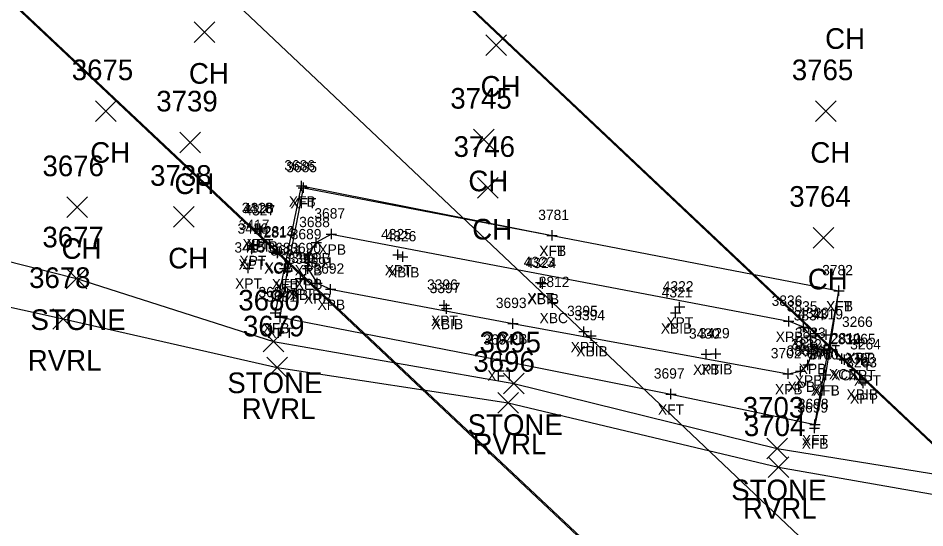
# Model space of a CAD drawing. Extents: x 1647574 to 1652703, y 212895 to 228670.
# Drawn here: x 1648808.6 to 1648896.4, y 227207.7 to 227257.1 of the extents above; entities that cross this region are included whole.
import ezdxf

# ---------------------------------------------------------------- set-up
doc = ezdxf.new("R2010")
doc.units = 0
for name, color, linetype in [('B_A', 7, 'Continuous'), ('B_I', 7, 'Continuous'), ('B_TIC', 7, 'Continuous'), ('BDC', 7, 'Continuous'), ('BELB', 7, 'Continuous'), ('BFT', 7, 'Continuous'), ('BSUBM', 7, 'Continuous'), ('L_A', 7, 'Continuous'), ('L_I', 7, 'Continuous'), ('L_TIC', 7, 'Continuous'), ('LASF', 7, 'Continuous'), ('LAWE', 7, 'Continuous')]:
    doc.layers.add(name, color=color, linetype=linetype)

msp = doc.modelspace()

# ---------------------------------------------------------------- linework, layer by layer
at = {"layer": 'B_TIC'}
for p, q in [((1648836.021, 227240.799), (1648836.096, 227240.799)), ((1648836.186, 227240.634), (1648836.262, 227240.634)), ((1648831.568, 227236.672), (1648831.644, 227236.672)), ((1648831.972, 227236.664), (1648832.048, 227236.664)), ((1648832.105, 227236.447), (1648832.18, 227236.447)), ((1648837.431, 227235.312), (1648837.506, 227235.312)), ((1648838.906, 227236.148), (1648838.982, 227236.148)), ((1648838.906, 227236.148), (1648838.982, 227236.148)), ((1648860.274, 227236.008), (1648860.35, 227236.008)), ((1648860.274, 227236.008), (1648860.35, 227236.008)), ((1648831.185, 227234.682), (1648831.261, 227234.682)), ((1648831.278, 227235.038), (1648831.354, 227235.038)), ((1648833.667, 227234.301), (1648833.743, 227234.301)), ((1648833.716, 227234.413), (1648833.792, 227234.413)), ((1648836.621, 227234.138), (1648836.696, 227234.138)), ((1648845.348, 227234.141), (1648845.423, 227234.141)), ((1648845.803, 227233.942), (1648845.878, 227233.942)), ((1648830.857, 227232.852), (1648830.932, 227232.852)), ((1648834.37, 227232.806), (1648834.445, 227232.806)), ((1648836.619, 227232.795), (1648836.694, 227232.795)), ((1648834.645, 227232.568), (1648834.72, 227232.568)), ((1648835.9, 227231.842), (1648835.975, 227231.842)), ((1648836.301, 227231.765), (1648836.376, 227231.765)), ((1648837.508, 227231.398), (1648837.583, 227231.398)), ((1648859.146, 227231.443), (1648859.222, 227231.443)), ((1648859.329, 227231.35), (1648859.404, 227231.35)), ((1648838.819, 227230.806), (1648838.895, 227230.806)), ((1648888.046, 227230.653), (1648888.122, 227230.653)), ((1648888.046, 227230.653), (1648888.122, 227230.653)), ((1648888.046, 227230.653), (1648888.122, 227230.653)), ((1648849.822, 227229.253), (1648849.898, 227229.253)), ((1648860.321, 227229.513), (1648860.396, 227229.513)), ((1648833.489, 227228.524), (1648833.564, 227228.524)), ((1648850.045, 227228.925), (1648850.121, 227228.925)), ((1648872.223, 227228.51), (1648872.299, 227228.51)), ((1648872.612, 227229.082), (1648872.688, 227229.082)), ((1648833.956, 227228.091), (1648834.031, 227228.091)), ((1648833.956, 227228.091), (1648834.031, 227228.091)), ((1648856.473, 227227.48), (1648856.549, 227227.48)), ((1648883.184, 227227.695), (1648883.259, 227227.695)), ((1648883.184, 227227.695), (1648883.259, 227227.695)), ((1648863.348, 227226.705), (1648863.424, 227226.705)), ((1648884.621, 227227.143), (1648884.697, 227227.143)), ((1648864.042, 227226.291), (1648864.118, 227226.291)), ((1648885.289, 227226.282), (1648885.364, 227226.282)), ((1648885.777, 227226.52), (1648885.853, 227226.52)), ((1648886.812, 227226.391), (1648886.887, 227226.391)), ((1648890.016, 227225.653), (1648890.091, 227225.653)), ((1648855.259, 227223.94), (1648855.334, 227223.94)), ((1648875.196, 227224.513), (1648875.271, 227224.513)), ((1648876.117, 227224.549), (1648876.192, 227224.549)), ((1648885.412, 227224.59), (1648885.487, 227224.59)), ((1648888.334, 227224.067), (1648888.409, 227224.067)), ((1648888.576, 227223.976), (1648888.651, 227223.976)), ((1648890.269, 227223.986), (1648890.345, 227223.986)), ((1648885.032, 227223.467), (1648885.108, 227223.467)), ((1648890.782, 227223.47), (1648890.858, 227223.47)), ((1648883.11, 227222.615), (1648883.186, 227222.615)), ((1648884.329, 227222.86), (1648884.405, 227222.86)), ((1648886.59, 227222.504), (1648886.665, 227222.504)), ((1648886.758, 227222.506), (1648886.834, 227222.506)), ((1648890.207, 227222.105), (1648890.282, 227222.105)), ((1648890.395, 227221.734), (1648890.471, 227221.734)), ((1648871.77, 227220.649), (1648871.845, 227220.649)), ((1648885.674, 227217.353), (1648885.75, 227217.353)), ((1648885.713, 227217.693), (1648885.788, 227217.693))]:
    msp.add_line(p, q, dxfattribs=at)
for points in [[(1648835.517, 227240.799), (1648836.517, 227240.799)], [(1648835.683, 227240.634), (1648836.683, 227240.634)], [(1648836.017, 227240.299), (1648836.017, 227241.299)], [(1648836.183, 227240.134), (1648836.183, 227241.134)], [(1648831.565, 227236.172), (1648831.565, 227237.172)], [(1648831.969, 227236.164), (1648831.969, 227237.164)], [(1648831.065, 227236.672), (1648832.065, 227236.672)], [(1648831.469, 227236.664), (1648832.469, 227236.664)], [(1648831.601, 227236.447), (1648832.601, 227236.447)], [(1648832.101, 227235.947), (1648832.101, 227236.947)], [(1648838.903, 227235.648), (1648838.903, 227236.648)], [(1648838.903, 227235.648), (1648838.903, 227236.648)], [(1648860.271, 227235.508), (1648860.271, 227236.508)], [(1648860.271, 227235.508), (1648860.271, 227236.508)], [(1648831.275, 227234.538), (1648831.275, 227235.538)], [(1648836.927, 227235.312), (1648837.927, 227235.312)], [(1648837.427, 227234.812), (1648837.427, 227235.812)], [(1648838.403, 227236.148), (1648839.403, 227236.148)], [(1648838.403, 227236.148), (1648839.403, 227236.148)], [(1648859.771, 227236.008), (1648860.771, 227236.008)], [(1648859.771, 227236.008), (1648860.771, 227236.008)], [(1648830.682, 227234.682), (1648831.682, 227234.682)], [(1648830.775, 227235.038), (1648831.775, 227235.038)], [(1648831.182, 227234.182), (1648831.182, 227235.182)], [(1648833.664, 227233.801), (1648833.664, 227234.801)], [(1648833.713, 227233.913), (1648833.713, 227234.913)], [(1648836.617, 227233.638), (1648836.617, 227234.638)], [(1648845.344, 227233.641), (1648845.344, 227234.641)], [(1648845.799, 227233.442), (1648845.799, 227234.442)], [(1648833.164, 227234.301), (1648834.164, 227234.301)], [(1648833.213, 227234.413), (1648834.213, 227234.413)], [(1648836.117, 227234.138), (1648837.117, 227234.138)], [(1648844.844, 227234.141), (1648845.844, 227234.141)], [(1648845.299, 227233.942), (1648846.299, 227233.942)], [(1648830.353, 227232.852), (1648831.353, 227232.852)], [(1648830.853, 227232.352), (1648830.853, 227233.352)], [(1648833.866, 227232.806), (1648834.866, 227232.806)], [(1648834.366, 227232.306), (1648834.366, 227233.306)], [(1648834.641, 227232.068), (1648834.641, 227233.068)], [(1648836.115, 227232.795), (1648837.115, 227232.795)], [(1648836.615, 227232.295), (1648836.615, 227233.295)], [(1648834.141, 227232.568), (1648835.141, 227232.568)], [(1648835.396, 227231.842), (1648836.396, 227231.842)], [(1648835.896, 227231.342), (1648835.896, 227232.342)], [(1648836.297, 227231.265), (1648836.297, 227232.265)], [(1648837.504, 227230.898), (1648837.504, 227231.898)], [(1648859.143, 227230.943), (1648859.143, 227231.943)], [(1648859.326, 227230.85), (1648859.326, 227231.85)], [(1648835.797, 227231.765), (1648836.797, 227231.765)], [(1648837.004, 227231.398), (1648838.004, 227231.398)], [(1648838.816, 227230.306), (1648838.816, 227231.306)], [(1648858.643, 227231.443), (1648859.643, 227231.443)], [(1648858.826, 227231.35), (1648859.826, 227231.35)], [(1648888.043, 227230.153), (1648888.043, 227231.153)], [(1648888.043, 227230.153), (1648888.043, 227231.153)], [(1648888.043, 227230.153), (1648888.043, 227231.153)], [(1648838.316, 227230.806), (1648839.316, 227230.806)], [(1648887.543, 227230.653), (1648888.543, 227230.653)], [(1648887.543, 227230.653), (1648888.543, 227230.653)], [(1648887.543, 227230.653), (1648888.543, 227230.653)], [(1648849.319, 227229.253), (1648850.319, 227229.253)], [(1648849.819, 227228.753), (1648849.819, 227229.753)], [(1648850.042, 227228.425), (1648850.042, 227229.425)], [(1648859.817, 227229.513), (1648860.817, 227229.513)], [(1648860.317, 227229.013), (1648860.317, 227230.013)], [(1648872.609, 227228.582), (1648872.609, 227229.582)], [(1648832.985, 227228.524), (1648833.985, 227228.524)], [(1648833.485, 227228.024), (1648833.485, 227229.024)], [(1648833.952, 227227.591), (1648833.952, 227228.591)], [(1648833.952, 227227.591), (1648833.952, 227228.591)], [(1648849.542, 227228.925), (1648850.542, 227228.925)], [(1648871.72, 227228.51), (1648872.72, 227228.51)], [(1648872.109, 227229.082), (1648873.109, 227229.082)], [(1648872.22, 227228.01), (1648872.22, 227229.01)], [(1648833.452, 227228.091), (1648834.452, 227228.091)], [(1648833.452, 227228.091), (1648834.452, 227228.091)], [(1648855.97, 227227.48), (1648856.97, 227227.48)], [(1648856.47, 227226.98), (1648856.47, 227227.98)], [(1648882.68, 227227.695), (1648883.68, 227227.695)], [(1648882.68, 227227.695), (1648883.68, 227227.695)], [(1648883.18, 227227.195), (1648883.18, 227228.195)], [(1648883.18, 227227.195), (1648883.18, 227228.195)], [(1648884.618, 227226.643), (1648884.618, 227227.643)], [(1648862.845, 227226.705), (1648863.845, 227226.705)], [(1648863.345, 227226.205), (1648863.345, 227227.205)], [(1648864.039, 227225.791), (1648864.039, 227226.791)], [(1648884.118, 227227.143), (1648885.118, 227227.143)], [(1648885.285, 227225.782), (1648885.285, 227226.782)], [(1648885.774, 227226.02), (1648885.774, 227227.02)], [(1648886.808, 227225.891), (1648886.808, 227226.891)], [(1648863.539, 227226.291), (1648864.539, 227226.291)], [(1648884.785, 227226.282), (1648885.785, 227226.282)], [(1648885.274, 227226.52), (1648886.274, 227226.52)], [(1648886.308, 227226.391), (1648887.308, 227226.391)], [(1648889.512, 227225.653), (1648890.512, 227225.653)], [(1648890.012, 227225.153), (1648890.012, 227226.153)], [(1648875.192, 227224.013), (1648875.192, 227225.013)], [(1648876.113, 227224.049), (1648876.113, 227225.049)], [(1648885.408, 227224.09), (1648885.408, 227225.09)], [(1648854.755, 227223.94), (1648855.755, 227223.94)], [(1648855.255, 227223.44), (1648855.255, 227224.44)], [(1648874.692, 227224.513), (1648875.692, 227224.513)], [(1648875.613, 227224.549), (1648876.613, 227224.549)], [(1648884.908, 227224.59), (1648885.908, 227224.59)], [(1648885.029, 227222.967), (1648885.029, 227223.967)], [(1648887.83, 227224.067), (1648888.83, 227224.067)], [(1648888.072, 227223.976), (1648889.072, 227223.976)], [(1648888.33, 227223.567), (1648888.33, 227224.567)], [(1648888.572, 227223.476), (1648888.572, 227224.476)], [(1648889.766, 227223.986), (1648890.766, 227223.986)], [(1648890.266, 227223.486), (1648890.266, 227224.486)], [(1648890.779, 227222.97), (1648890.779, 227223.97)], [(1648883.107, 227222.115), (1648883.107, 227223.115)], [(1648884.326, 227222.36), (1648884.326, 227223.36)], [(1648884.529, 227223.467), (1648885.529, 227223.467)], [(1648890.279, 227223.47), (1648891.279, 227223.47)], [(1648882.607, 227222.615), (1648883.607, 227222.615)], [(1648883.826, 227222.86), (1648884.826, 227222.86)], [(1648886.086, 227222.504), (1648887.086, 227222.504)], [(1648886.255, 227222.506), (1648887.255, 227222.506)], [(1648886.586, 227222.004), (1648886.586, 227223.004)], [(1648886.755, 227222.006), (1648886.755, 227223.006)], [(1648890.203, 227221.605), (1648890.203, 227222.605)], [(1648890.392, 227221.234), (1648890.392, 227222.234)], [(1648889.703, 227222.105), (1648890.703, 227222.105)], [(1648889.892, 227221.734), (1648890.892, 227221.734)], [(1648871.266, 227220.649), (1648872.266, 227220.649)], [(1648871.766, 227220.149), (1648871.766, 227221.149)], [(1648885.671, 227216.853), (1648885.671, 227217.853)], [(1648885.709, 227217.193), (1648885.709, 227218.193)], [(1648885.171, 227217.353), (1648886.171, 227217.353)], [(1648885.209, 227217.693), (1648886.209, 227217.693)]]:
    msp.add_lwpolyline(points, dxfattribs=at)
at = {"layer": 'BDC'}
for points in [[(1648650.624, 227406.773), (1648690.525, 227369.254), (1648733.472, 227328.732), (1648776.312, 227288.32), (1648833.664, 227234.301), (1648891.231, 227180.054), (1648955.856, 227118.961), (1649002.635, 227075.018), (1649045.277, 227034.596)], [(1648651.076, 227406.804), (1648690.742, 227369.256), (1648733.458, 227328.853), (1648776.322, 227288.427), (1648833.713, 227234.413), (1648891.304, 227180.165), (1648955.952, 227119.198), (1649002.814, 227075.033), (1649045.282, 227034.879)], [(1648705.852, 227396.154), (1648745.059, 227359.411), (1648787.916, 227318.711), (1648830.863, 227278.3), (1648888.33, 227224.067), (1648945.958, 227169.85), (1649010.577, 227108.866), (1649057.241, 227064.803), (1649099.962, 227024.603)], [(1648705.902, 227396.256), (1648745.142, 227359.215), (1648788.072, 227318.717), (1648831.078, 227278.232), (1648888.572, 227223.976), (1648945.897, 227169.932), (1649010.764, 227109.119), (1649057.374, 227064.845), (1649100.019, 227024.673)]]:
    msp.add_lwpolyline(points, dxfattribs=at)
at = {"layer": 'BELB'}
msp.add_lwpolyline([(1648676.128, 227401.909), (1648716.738, 227364.514), (1648759.552, 227324.27), (1648803.456, 227283.214), (1648860.317, 227229.513), (1648917.836, 227175.012), (1648982.231, 227114.435), (1649029.643, 227069.952), (1649071.001, 227030.272)], dxfattribs=at)
at = {"layer": 'BFT'}
for points in [[(1648833.485, 227228.524), (1648834.366, 227232.806), (1648836.017, 227240.799), (1648860.271, 227236.008)], [(1648833.952, 227228.091), (1648834.641, 227232.568), (1648836.183, 227240.634), (1648860.271, 227236.008), (1648888.043, 227230.653)], [(1648833.952, 227228.091), (1648855.255, 227223.94), (1648871.766, 227220.649), (1648885.709, 227217.693), (1648886.586, 227222.504), (1648888.043, 227230.653)], [(1648885.671, 227217.353), (1648886.755, 227222.506), (1648888.043, 227230.653)]]:
    msp.add_lwpolyline(points, dxfattribs=at)
at = {"layer": 'BSUBM'}
for points in [[(1648838.903, 227236.148), (1648837.427, 227235.312), (1648836.617, 227234.138), (1648836.615, 227232.795), (1648837.504, 227231.398), (1648838.816, 227230.806), (1648856.47, 227227.48), (1648883.107, 227222.615), (1648884.326, 227222.86), (1648885.029, 227223.467), (1648885.408, 227224.59), (1648885.285, 227226.282), (1648884.618, 227227.143), (1648883.18, 227227.695)], [(1648838.903, 227236.148), (1648883.18, 227227.695)]]:
    msp.add_lwpolyline(points, dxfattribs=at)
at = {"layer": 'L_TIC'}
for points in [[(1648825.616, 227254.702), (1648827.616, 227256.702)], [(1648827.616, 227254.702), (1648825.616, 227256.702)], [(1648853.857, 227253.45), (1648855.857, 227255.45)], [(1648855.857, 227253.45), (1648853.857, 227255.45)], [(1648816.064, 227247.043), (1648818.064, 227249.043)], [(1648818.064, 227247.043), (1648816.064, 227249.043)], [(1648885.782, 227247.044), (1648887.782, 227249.044)], [(1648887.782, 227247.044), (1648885.782, 227249.044)], [(1648824.212, 227244.017), (1648826.212, 227246.017)], [(1648826.212, 227244.017), (1648824.212, 227246.017)], [(1648852.671, 227244.288), (1648854.671, 227246.288)], [(1648854.671, 227244.288), (1648852.671, 227246.288)], [(1648853.043, 227239.617), (1648855.043, 227241.617)], [(1648855.043, 227239.617), (1648853.043, 227241.617)], [(1648813.284, 227237.746), (1648815.284, 227239.746)], [(1648815.284, 227237.746), (1648813.284, 227239.746)], [(1648823.607, 227236.817), (1648825.607, 227238.817)], [(1648825.607, 227236.817), (1648823.607, 227238.817)], [(1648885.538, 227234.787), (1648887.538, 227236.787)], [(1648887.538, 227234.787), (1648885.538, 227236.787)], [(1648813.223, 227230.854), (1648815.223, 227232.854)], [(1648815.223, 227230.854), (1648813.223, 227232.854)], [(1648811.936, 227226.92), (1648813.936, 227228.92)], [(1648813.936, 227226.92), (1648811.936, 227228.92)], [(1648832.279, 227224.74), (1648834.279, 227226.74)], [(1648834.279, 227224.74), (1648832.279, 227226.74)], [(1648832.651, 227222.234), (1648834.651, 227224.234)], [(1648834.651, 227222.234), (1648832.651, 227224.234)], [(1648855.547, 227220.689), (1648857.547, 227222.689)], [(1648857.547, 227220.689), (1648855.547, 227222.689)], [(1648855.007, 227218.814), (1648857.007, 227220.814)], [(1648857.007, 227218.814), (1648855.007, 227220.814)], [(1648881.063, 227214.369), (1648883.063, 227216.369)], [(1648883.063, 227214.369), (1648881.063, 227216.369)], [(1648881.174, 227212.58), (1648883.174, 227214.58)], [(1648883.174, 227212.58), (1648881.174, 227214.58)]]:
    msp.add_lwpolyline(points, dxfattribs=at)
at = {"layer": 'LASF'}
msp.add_lwpolyline([(1648499.797, 227390.788), (1648534.237, 227361.964), (1648564.139, 227335.998), (1648594.151, 227310.22), (1648628.599, 227293.401), (1648654.269, 227279.63), (1648686.156, 227265.624), (1648717.135, 227256.764), (1648740.627, 227248.949), (1648765.894, 227244.077), (1648814.223, 227231.854), (1648833.279, 227225.74), (1648856.547, 227221.689), (1648882.063, 227215.369), (1648909.355, 227210.97), (1648936.503, 227203.804), (1648961.566, 227198.174), (1648983.303, 227192.864), (1648997.705, 227192.889), (1649002.003, 227200.334)], dxfattribs=at)
at = {"layer": 'LAWE'}
msp.add_lwpolyline([(1648476.378, 227405.216), (1648496.153, 227388.221), (1648530.655, 227356.871), (1648567.867, 227325.979), (1648591.316, 227307.766), (1648628.319, 227290.488), (1648653.198, 227277.298), (1648685.977, 227263.737), (1648715.079, 227253.44), (1648739.533, 227246.568), (1648765.368, 227238.448), (1648812.936, 227227.92), (1648833.651, 227223.234), (1648856.007, 227219.814), (1648882.174, 227213.58), (1648908.492, 227208.957)], dxfattribs=at)

# ---------------------------------------------------------------- texts
at = {"layer": 'B_A'}
for s, p in [('XFB', (1648834.777, 227238.799)), ('XFT', (1648834.927, 227238.634)), ('XPT', (1648830.285, 227234.672)), ('XBIB', (1648830.672, 227234.447)), ('XPT', (1648830.689, 227234.664)), ('XPB', (1648837.639, 227234.148)), ('XPB', (1648837.639, 227234.148)), ('XFT', (1648859.015, 227234.008)), ('XFB', (1648859.031, 227234.008)), ('XPT', (1648829.902, 227232.682)), ('XPT', (1648829.995, 227233.038)), ('XPB', (1648836.163, 227233.312)), ('XCT', (1648832.384, 227232.301)), ('XCB', (1648832.449, 227232.413)), ('XPB', (1648835.354, 227232.138)), ('XPT', (1648844.065, 227232.141)), ('XBIB', (1648844.37, 227231.942)), ('XPT', (1648829.574, 227230.852)), ('XFB', (1648833.126, 227230.806)), ('XPB', (1648835.351, 227230.795)), ('XFT', (1648833.385, 227230.568)), ('XPT', (1648834.617, 227229.842)), ('XBIB', (1648834.868, 227229.765)), ('XPB', (1648836.24, 227229.398)), ('XPT', (1648857.863, 227229.443)), ('XBIB', (1648857.896, 227229.35)), ('XPB', (1648837.552, 227228.806)), ('XFT', (1648886.787, 227228.653)), ('XFT', (1648886.787, 227228.653)), ('XFB', (1648886.802, 227228.653)), ('XBC', (1648859.053, 227227.513)), ('XFB', (1648832.245, 227226.524)), ('XPT', (1648848.539, 227227.253)), ('XBIB', (1648848.613, 227226.925)), ('XBIB', (1648870.791, 227226.51)), ('XPT', (1648871.329, 227227.082)), ('XFT', (1648832.696, 227226.091)), ('XFT', (1648832.696, 227226.091)), ('XPB', (1648881.917, 227225.695)), ('XPB', (1648881.917, 227225.695)), ('XPB', (1648855.206, 227225.48)), ('XPT', (1648862.065, 227224.705)), ('XPB', (1648883.354, 227225.143)), ('XBIB', (1648862.61, 227224.291)), ('XPB', (1648884.022, 227224.282)), ('XBIB', (1648884.345, 227224.52)), ('XPT', (1648885.529, 227224.391)), ('XPT', (1648888.733, 227223.653)), ('XPT', (1648873.913, 227222.513)), ('XBIB', (1648874.684, 227222.549)), ('XPB', (1648884.144, 227222.59)), ('XCB', (1648887.066, 227222.067)), ('XFT', (1648853.999, 227221.94)), ('XPB', (1648883.765, 227221.467)), ('XCT', (1648887.293, 227221.976)), ('XPT', (1648888.986, 227221.986)), ('XPT', (1648889.499, 227221.47)), ('XPB', (1648881.843, 227220.615)), ('XPB', (1648883.062, 227220.86)), ('XFT', (1648885.331, 227220.504)), ('XFB', (1648885.515, 227220.506)), ('XBIB', (1648888.774, 227220.105)), ('XPT', (1648889.112, 227219.734)), ('XFT', (1648870.511, 227218.649)), ('XFB', (1648884.431, 227215.353)), ('XFT', (1648884.453, 227215.693))]:
    msp.add_text(s, height=1, dxfattribs=at).set_placement(p)
at = {"layer": 'B_I'}
for s, p in [('3686', (1648834.336, 227242.299)), ('3685', (1648834.529, 227242.134)), ('3418', (1648830.218, 227238.172)), ('4328', (1648830.339, 227238.164)), ('4327', (1648830.472, 227237.947)), ('3687', (1648837.249, 227237.648)), ('3687', (1648837.249, 227237.648)), ('3781', (1648858.924, 227237.508)), ('3781', (1648858.924, 227237.508)), ('3416', (1648829.808, 227236.182)), ('3417', (1648829.929, 227236.538)), ('3688', (1648835.774, 227236.812)), ('2814', (1648832.317, 227235.801)), ('2813', (1648832.367, 227235.913)), ('3689', (1648834.96, 227235.638)), ('4325', (1648843.714, 227235.641)), ('4326', (1648844.142, 227235.442)), ('3415', (1648829.507, 227234.352)), ('3683', (1648832.713, 227234.306)), ('3690', (1648834.918, 227234.295)), ('3684', (1648832.988, 227234.068)), ('3399', (1648834.263, 227233.342)), ('3398', (1648834.668, 227233.265)), ('3691', (1648836.134, 227232.898)), ('4323', (1648857.513, 227232.943)), ('4324', (1648857.696, 227232.85)), ('3692', (1648837.162, 227232.306)), ('3782', (1648886.413, 227232.153)), ('3782', (1648886.413, 227232.153)), ('3782', (1648886.413, 227232.153)), ('2812', (1648858.971, 227231.013)), ('3682', (1648831.832, 227230.024)), ('3396', (1648848.161, 227230.753)), ('3397', (1648848.412, 227230.425)), ('4321', (1648870.873, 227230.01)), ('4322', (1648870.979, 227230.582)), ('3681', (1648832.582, 227229.591)), ('3681', (1648832.582, 227229.591)), ('3836', (1648881.523, 227229.195)), ('3836', (1648881.523, 227229.195)), ('3693', (1648854.816, 227228.98)), ('3395', (1648861.715, 227228.205)), ('3835', (1648882.988, 227228.643)), ('3394', (1648862.409, 227227.791)), ('3834', (1648883.656, 227227.782)), ('4320', (1648884.101, 227228.02)), ('4319', (1648885.458, 227227.891)), ('3266', (1648888.331, 227227.153)), ('3430', (1648873.519, 227226.013)), ('3429', (1648874.48, 227226.049)), ('3833', (1648883.778, 227226.09)), ('2811', (1648887.267, 227225.567)), ('3694', (1648853.602, 227225.44)), ('3832', (1648883.399, 227224.967)), ('2810', (1648887.182, 227225.476)), ('3265', (1648888.612, 227225.486)), ('3264', (1648889.125, 227224.97)), ('3702', (1648881.438, 227224.115)), ('3831', (1648882.979, 227224.36)), ('3700', (1648885.042, 227224.006)), ('3701', (1648885.201, 227224.004)), ('3393', (1648888.574, 227223.605)), ('3263', (1648888.738, 227223.234)), ('3697', (1648870.113, 227222.149)), ('3699', (1648884.014, 227218.853)), ('3698', (1648884.056, 227219.193))]:
    msp.add_text(s, height=1, dxfattribs=at).set_placement(p)
at = {"layer": 'L_A'}
for s, p in [('CH', (1648886.7, 227254.077)), ('CH', (1648825.104, 227250.702)), ('CH', (1648853.345, 227249.45)), ('CH', (1648815.552, 227243.043)), ('CH', (1648885.27, 227243.044)), ('CH', (1648823.7, 227240.017)), ('CH', (1648852.159, 227240.288)), ('CH', (1648852.531, 227235.617)), ('CH', (1648812.772, 227233.746)), ('CH', (1648823.096, 227232.817)), ('CH', (1648885.026, 227230.787)), ('STONE', (1648809.767, 227226.854)), ('RVRL', (1648809.503, 227222.92)), ('STONE', (1648828.822, 227220.74)), ('RVRL', (1648830.218, 227218.234)), ('STONE', (1648852.09, 227216.689)), ('RVRL', (1648852.574, 227214.814)), ('STONE', (1648877.606, 227210.369)), ('RVRL', (1648878.741, 227208.58))]:
    msp.add_text(s, height=2, dxfattribs=at).set_placement(p)
at = {"layer": 'L_I'}
for s, p in [('3675', (1648813.757, 227251.043)), ('3765', (1648883.475, 227251.044)), ('3745', (1648850.411, 227248.288)), ('3739', (1648821.944, 227248.017)), ('3746', (1648850.728, 227243.617)), ('3676', (1648810.922, 227241.746)), ('3738', (1648821.348, 227240.817)), ('3764', (1648883.231, 227238.787)), ('3677', (1648810.916, 227234.854)), ('3678', (1648809.629, 227230.92)), ('3680', (1648829.885, 227228.74)), ('3679', (1648830.337, 227226.234)), ('3695', (1648853.24, 227224.689)), ('3696', (1648852.645, 227222.814)), ('3703', (1648878.725, 227218.369)), ('3704', (1648878.835, 227216.58))]:
    msp.add_text(s, height=2, dxfattribs=at).set_placement(p)

doc.saveas('drawing.dxf')
